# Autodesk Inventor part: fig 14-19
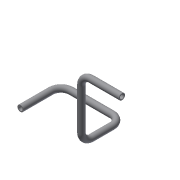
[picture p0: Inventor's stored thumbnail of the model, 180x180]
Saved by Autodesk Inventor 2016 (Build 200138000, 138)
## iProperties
Created: 2005-03
Part Number: fig 14-19
Document SubType Name: Modeling
Designer: CADCIM
Manufacturer: Standard
Standards Organization: Custom
Density: 1 g/cm^3
Material: Generic
Appearance: Default
Author: CADCIM
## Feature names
1. Sweep1
## Parameters: d9 = 6 mm, d10 = 4 mm, d11 = 0, d12 = 0
